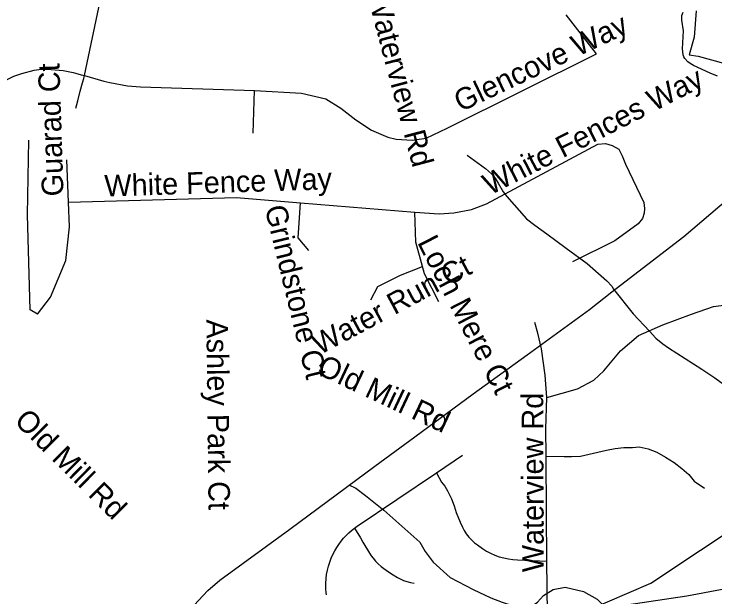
# Model space of a CAD drawing. Extents: x 1662474 to 1856135, y 779280 to 917889.
# Drawn here: x 1701744 to 1704832, y 829158 to 831727 of the extents above; entities that cross this region are included whole.
import ezdxf

# ---------------------------------------------------------------- set-up
doc = ezdxf.new("R2010")
doc.units = 0
for name, color, linetype in [('Exist Hydrographic Lake Shore', 7, 'Continuous'), ('Exist Hydrographic Misc Water Feature', 7, 'Continuous'), ('Exist Road Non-System Type 51', 7, 'Continuous'), ('Exist Road Non-System Type 51 Label', 7, 'Continuous'), ('Exist Utilities Electrical Transmission Line', 7, 'Continuous'), ('Old_Level_44', 7, 'Continuous')]:
    doc.layers.add(name, color=color, linetype=linetype)

msp = doc.modelspace()

# ---------------------------------------------------------------- linework, layer by layer
at = {"layer": 'Exist Hydrographic Lake Shore'}
msp.add_lwpolyline([(1704842.4, 831453.2), (1704810.6, 831465.8), (1704737.8, 831499.6), (1704723, 831508.6), (1704712.5, 831516.4), (1704699.6, 831530.3), (1704694.9, 831538.2), (1704691.8, 831546.9), (1704688.6, 831573.4), (1704692.8, 831652.4), (1704686, 831699.1), (1704685.5, 831714.1), (1704686.5, 831720.4), (1704691.5, 831734.2)], dxfattribs=at)
at = {"layer": 'Exist Hydrographic Misc Water Feature'}
for points in [[(1703740.2, 831105.3), (1703821.7, 831046.2), (1703847.2, 831021.8), (1703863.1, 831003.5), (1703876.9, 830981.9), (1703898.5, 830943.7), (1703914.3, 830922.8), (1704001.2, 830824.2), (1704039, 830795.6), (1704090.5, 830758.4), (1704177, 830695.1), (1704268.2, 830626.7), (1704355.2, 830551.1), (1704377.5, 830526.9)], [(1704377.5, 830526.9), (1704384.7, 830514.4), (1704472.1, 830406), (1704543.7, 830329), (1704571.7, 830298.9), (1704601.5, 830272.9), (1704627.6, 830255.1)], [(1704627.6, 830255.1), (1704773.5, 830161.9), (1704831.1, 830123.8), (1704885, 830083.3), (1704920.9, 830049.7), (1704972.8, 830010.9), (1705028.7, 829972.9), (1705110.7, 829928.5), (1705172.6, 829900.2), (1705232.5, 829876), (1705260.4, 829857.4), (1705274.2, 829842.3)], [(1703219.3, 829651.9), (1703249.2, 829638.2), (1703292.6, 829605.3), (1703373.7, 829540.4), (1703532.2, 829400.2), (1703555.5, 829357.9), (1703590.9, 829311.2), (1703665.9, 829244), (1703767.3, 829191), (1703844.9, 829154.1), (1703894.5, 829135.1), (1703940.2, 829120.2), (1703988.3, 829114.3), (1704020.3, 829115.3), (1704050.5, 829135.2), (1704076.9, 829165), (1704119.4, 829190.5), (1704171.5, 829201.7), (1704253.2, 829182.8), (1704312.7, 829147.9), (1704363.5, 829098.5)]]:
    msp.add_lwpolyline(points, dxfattribs=at)
at = {"layer": 'Exist Road Non-System Type 51'}
for p, q in [((1702797.2, 831200.9), (1702803.6, 831389.7)), ((1701984.6, 830897.5), (1701977.1, 831083.9)), ((1703005.6, 830895.4), (1703510.1, 830853.7)), ((1703604.6, 829705.7), (1703719.1, 829783.1)), ((1704096.8, 828731.9), (1704091.8, 829315.4))]:
    msp.add_line(p, q, dxfattribs=at)
for points in [[(1702054.5, 831455.2), (1702123.6, 831783.4), (1702140.9, 831832.7), (1702168.9, 831883.4), (1702202, 831928.5), (1702239.4, 831959.4), (1702286.5, 831991.5), (1702338.5, 832011.4), (1702382.6, 832023.5), (1702434.9, 832030.4), (1702482.6, 832040.9), (1702528, 832056.9), (1702573.4, 832083.6), (1702602.9, 832109), (1702629.1, 832136.9)], [(1703651.4, 831224), (1704309.9, 831550.5), (1704175.8, 831723.2)], [(1701356.9, 831415.6), (1701385, 831402.8), (1701409.4, 831402.5), (1701437.5, 831401.4), (1701469.8, 831399.4), (1701505.4, 831398.9), (1701545.1, 831398.6), (1701583.6, 831400.4), (1701621.1, 831408), (1701690.2, 831425.9), (1701743, 831452.1), (1701778.6, 831465), (1701832.2, 831478.9), (1701864.2, 831483.1), (1701890.5, 831483.9), (1701960, 831478.1), (1701982.9, 831473.1), (1702005.1, 831468.4), (1702025.4, 831462.6), (1702039.9, 831458.9), (1702054.5, 831455.2)], [(1702016.1, 831311.2), (1702024.4, 831343.4), (1702035.4, 831386.8), (1702045.9, 831422.7), (1702051.6, 831442.7), (1702054.5, 831455.2)], [(1702054.5, 831455.2), (1702139.6, 831431.1), (1702166.1, 831425.1), (1702244, 831410.4), (1702301.8, 831406.2), (1702803.6, 831389.7)], [(1702803.6, 831389.7), (1703010.1, 831377.6), (1703117.2, 831353.2), (1703184.1, 831311.2), (1703249.2, 831260.2), (1703318.9, 831214.6), (1703390.8, 831183.6), (1703427.1, 831174.9), (1703498.6, 831170.2), (1703559.5, 831179.9), (1703651.4, 831224)], [(1701847.4, 830403.9), (1701815.6, 830423.2), (1701803.6, 830841.4), (1701809.6, 831171.2)], [(1703824.9, 830890.2), (1704315.1, 831152.7), (1704349.5, 831155.8), (1704379.6, 831147.7), (1704408.6, 831131.7), (1704422.4, 831102.2), (1704438.1, 831065.5), (1704518.2, 830896.5), (1704521.4, 830869.2), (1704520.6, 830849.5), (1704511.9, 830825.6), (1704493.4, 830802.2), (1704390.1, 830727.7), (1704203.6, 830634.2)], [(1701984.6, 830897.5), (1702723.5, 830917.8), (1703005.6, 830895.4)], [(1701847.4, 830403.9), (1701905.4, 830478.4), (1701972.4, 830641.1), (1701989.1, 830789.4), (1701984.6, 830897.5)], [(1703042.4, 830684.2), (1702995.8, 830741.1), (1703005.6, 830895.4)], [(1703510.1, 830853.7), (1703617.5, 830845.9), (1703681.8, 830850.5), (1703760, 830865), (1703824.9, 830890.2)], [(1703543.1, 830613.9), (1703513.9, 830721.2), (1703510.1, 830853.7)], [(1703316.4, 830466.9), (1703347.1, 830526.7), (1703445.9, 830575.5), (1703543.1, 830613.9)], [(1703614.9, 830458.2), (1703552.1, 830581.5), (1703543.1, 830613.9)], [(1704091.2, 830036.9), (1704226.6, 830075.5), (1704298.6, 830113), (1704342.4, 830154.8), (1704415.1, 830243.2), (1704495.4, 830309.9), (1704602.8, 830356.9), (1704728.8, 830404.6), (1704825.6, 830437.9), (1704902.8, 830448.4), (1704995.1, 830423.5)], [(1704091.2, 830036.9), (1704083.1, 830134.9), (1704067.4, 830251.1), (1704052.1, 830320.4), (1704037.9, 830366.9)], [(1704087.6, 829778.4), (1704086.5, 829898.6), (1704091.2, 830036.9)], [(1704087.6, 829778.4), (1704167.9, 829776.9), (1704200.4, 829776.9), (1704238.8, 829779.2), (1704316.1, 829796.2), (1704354.5, 829804.4), (1704392, 829812.8), (1704430.9, 829816.7), (1704469.1, 829816.7), (1704498.4, 829819.4), (1704537.4, 829810.4), (1704575.8, 829795.4), (1704614.6, 829773.9), (1704651.6, 829750), (1704685.6, 829724.6), (1704717.1, 829697.5), (1704739.8, 829668.9), (1704785.4, 829636.9)], [(1704091.8, 829315.4), (1704089.6, 829530.9), (1704087.6, 829778.4)], [(1703243.5, 829461.1), (1703256.1, 829470), (1703604.6, 829705.7)], [(1703604.6, 829705.7), (1703627.8, 829664.5), (1703641.4, 829645.6), (1703654, 829625.9), (1703663.1, 829608), (1703671.2, 829589.9), (1703682.6, 829560), (1703691.5, 829530.1), (1703709.4, 829487.1), (1703719.1, 829465.5), (1703726.9, 829451.1), (1703736.4, 829435.6), (1703747.9, 829421.2), (1703760.2, 829408.4), (1703773.1, 829396.5), (1703785.1, 829387.4), (1703807.8, 829371.4), (1703825.4, 829360.5), (1703843.5, 829350.9), (1703862.4, 829342.7), (1703881.8, 829335.6), (1703901.1, 829329.9), (1703921.6, 829325.7), (1703941.9, 829323.2), (1703961.4, 829321.7), (1704091.8, 829315.4)], [(1703120.4, 829167.4), (1703118.9, 829178.2), (1703117.8, 829192.6), (1703117.5, 829219.6), (1703118.9, 829238.5), (1703121.1, 829257.2), (1703124.6, 829275.5), (1703129, 829293.6), (1703134.6, 829311.4), (1703141.4, 829328.8), (1703149, 829345.9), (1703157.6, 829362.1), (1703165.8, 829376), (1703174.4, 829388.9), (1703185.1, 829403.4), (1703196, 829416.7), (1703207, 829428.8), (1703218.5, 829440.4), (1703230.6, 829450.6), (1703243.5, 829461.1)], [(1703243.5, 829461.1), (1703270.2, 829418.2), (1703281, 829399.7), (1703310.1, 829350.6), (1703317.5, 829339), (1703325.6, 829328.8), (1703336.6, 829315.9), (1703348.5, 829303.9), (1703361.9, 829292), (1703372.9, 829283.7), (1703393.4, 829269.2), (1703414.1, 829255.6), (1703433.2, 829243.8), (1703444.5, 829237.7), (1703459.5, 829231.2), (1703474.6, 829225.9), (1703490.1, 829221.9), (1703506.1, 829218.9)]]:
    msp.add_lwpolyline(points, dxfattribs=at)
at = {"layer": 'Exist Utilities Electrical Transmission Line'}
for points in [[(1704330.5, 829125.1), (1704357.7, 829137.4), (1704549.9, 829219.5), (1704987.4, 829509.1), (1705656.6, 829944.3), (1706235.2, 830322.3), (1706743.5, 830657.3), (1707181, 830946.8), (1707763.6, 831326.9), (1708303.7, 831673.4), (1708928.7, 832081.1), (1709620.3, 832536.3), (1710291.6, 832975.4), (1711027.5, 833455.9), (1711648.5, 833863.6), (1712239.1, 834253.8), (1713005.3, 834756), (1713847.9, 835307.5)], [(1702457, 829035.6), (1702598.5, 829186.2), (1702651.1, 829231.6), (1702959.6, 829456.3), (1703332.8, 829734.2), (1703510.4, 829864.3), (1703766.6, 830053.6), (1704004.4, 830225.1), (1704278.8, 830424.2), (1704376.8, 830502), (1704694.3, 830746.7), (1705090.4, 831084.8), (1705419.5, 831351.4), (1705966.5, 831571.8), (1706414.8, 831743.3), (1706617.1, 831947.3), (1707052.3, 832388.9), (1707471.1, 832804.7), (1707827.4, 833175.3)], [(1704330.5, 829125.1), (1704363.9, 829125.2), (1704441.7, 829122.8), (1704707.5, 829163.8), (1705527.8, 829317.2), (1706167.7, 829434.6), (1706717.3, 829530.9), (1706941.1, 829496.5), (1707139, 829464.5), (1707886.3, 829332.6), (1708789.5, 829173.1), (1709700.6, 829009.5), (1710597.6, 828852.2), (1711504.6, 828682.4), (1712417.9, 828528.9), (1713335, 828365.2)]]:
    msp.add_lwpolyline(points, dxfattribs=at)
at = {"layer": 'Old_Level_44'}
msp.add_lwpolyline([(1704748.5, 831740.6), (1704739.6, 831625.1), (1704717.7, 831546.7), (1704757.3, 831540.8), (1704875.6, 831508.1)], dxfattribs=at)

# ---------------------------------------------------------------- texts
at = {"layer": 'Exist Road Non-System Type 51 Label'}
for s, rotation, p in [('Waterview Rd', 284.8063, (1703299.3, 831809.6)), ('Glencove Way', 25.3415, (1703711, 831293.3)), ('Guarad Ct', 91.789, (1701962.3, 830924.6)), ('White Fences Way', 27.0829, (1703840.7, 830926.7)), ('White Fence Way', 1.8818, (1702143.8, 830921.8)), ('Grindstone Ct', 283.6642, (1702847.7, 830872.9)), ('Loch Mere Ct', 297.2293, (1703518.7, 830720.6)), ('Water Run Ct', 28.1914, (1703090, 830222.6)), ('Ashley Park Ct', 270.6615, (1702591.3, 830380.9)), ('Old Mill Rd', 334.7564, (1703073.2, 830143.7)), ('Waterview Rd', 90.2072, (1704077.9, 829267.5)), ('Old Mill Rd', 315.2505, (1701740.6, 829929.2))]:
    msp.add_text(s, height=95, rotation=rotation, dxfattribs=at).set_placement(p)

doc.saveas('drawing.dxf')
